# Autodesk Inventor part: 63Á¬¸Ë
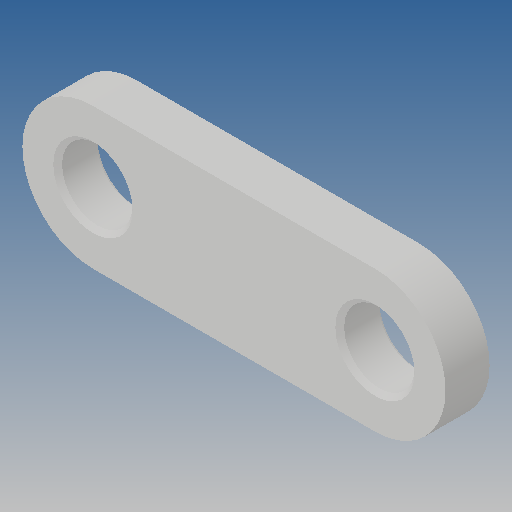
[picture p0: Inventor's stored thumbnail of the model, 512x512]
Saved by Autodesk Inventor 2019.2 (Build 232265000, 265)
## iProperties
Created: 2013-07
Part Number: 63Á¬¸Ë
Material: Ogólny
Document SubType Name: Modeling
Designer: CADENGINEERING4
Density: 1 g/cm^3
Appearance: Domyślna
Author: CADENGINEERING4
Revision Number: ÈÎºÎ
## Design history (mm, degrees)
feature "µ¹½Ç1"
node "Bryła1"
